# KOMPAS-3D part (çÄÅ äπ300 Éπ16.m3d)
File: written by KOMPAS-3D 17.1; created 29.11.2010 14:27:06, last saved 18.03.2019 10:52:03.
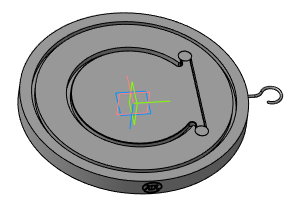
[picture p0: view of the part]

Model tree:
1. Плоскость XY
2. Плоскость ZX
3. Плоскость ZY
4. Ось X
5. Ось Y
6. Ось Z
7. Начало координат
8. Операция без истории:2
